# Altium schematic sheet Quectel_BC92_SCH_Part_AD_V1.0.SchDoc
size 840 x 594 mm
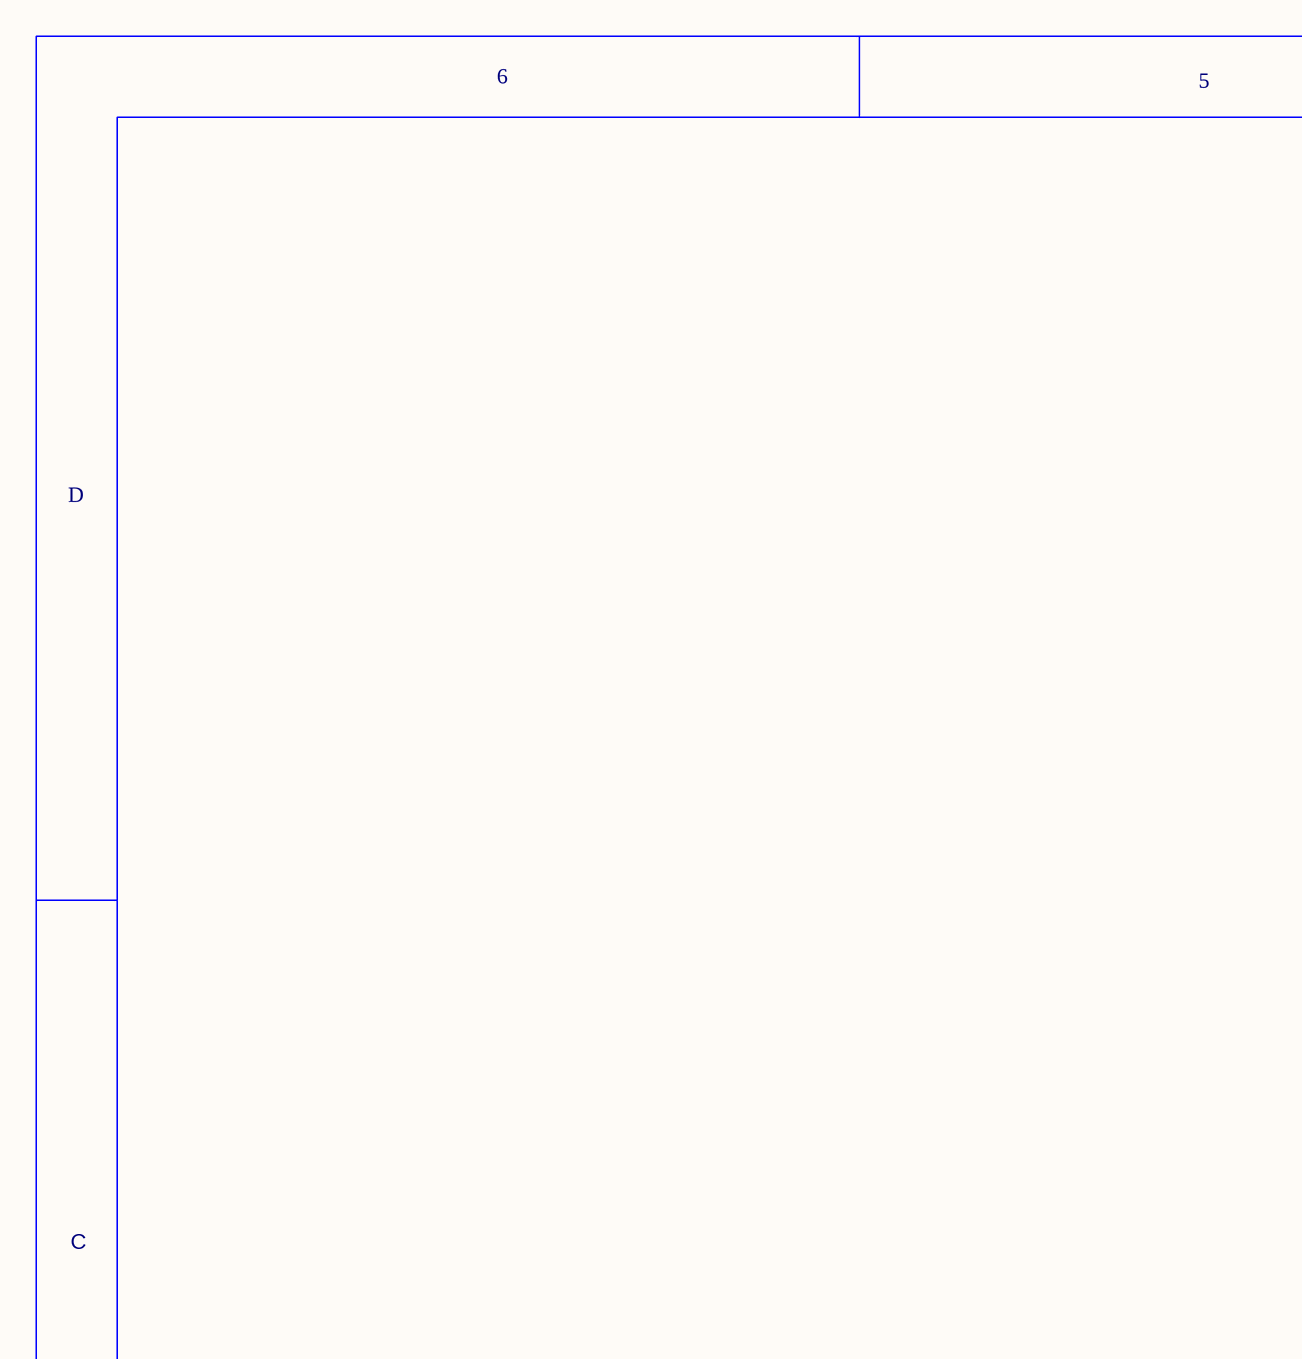
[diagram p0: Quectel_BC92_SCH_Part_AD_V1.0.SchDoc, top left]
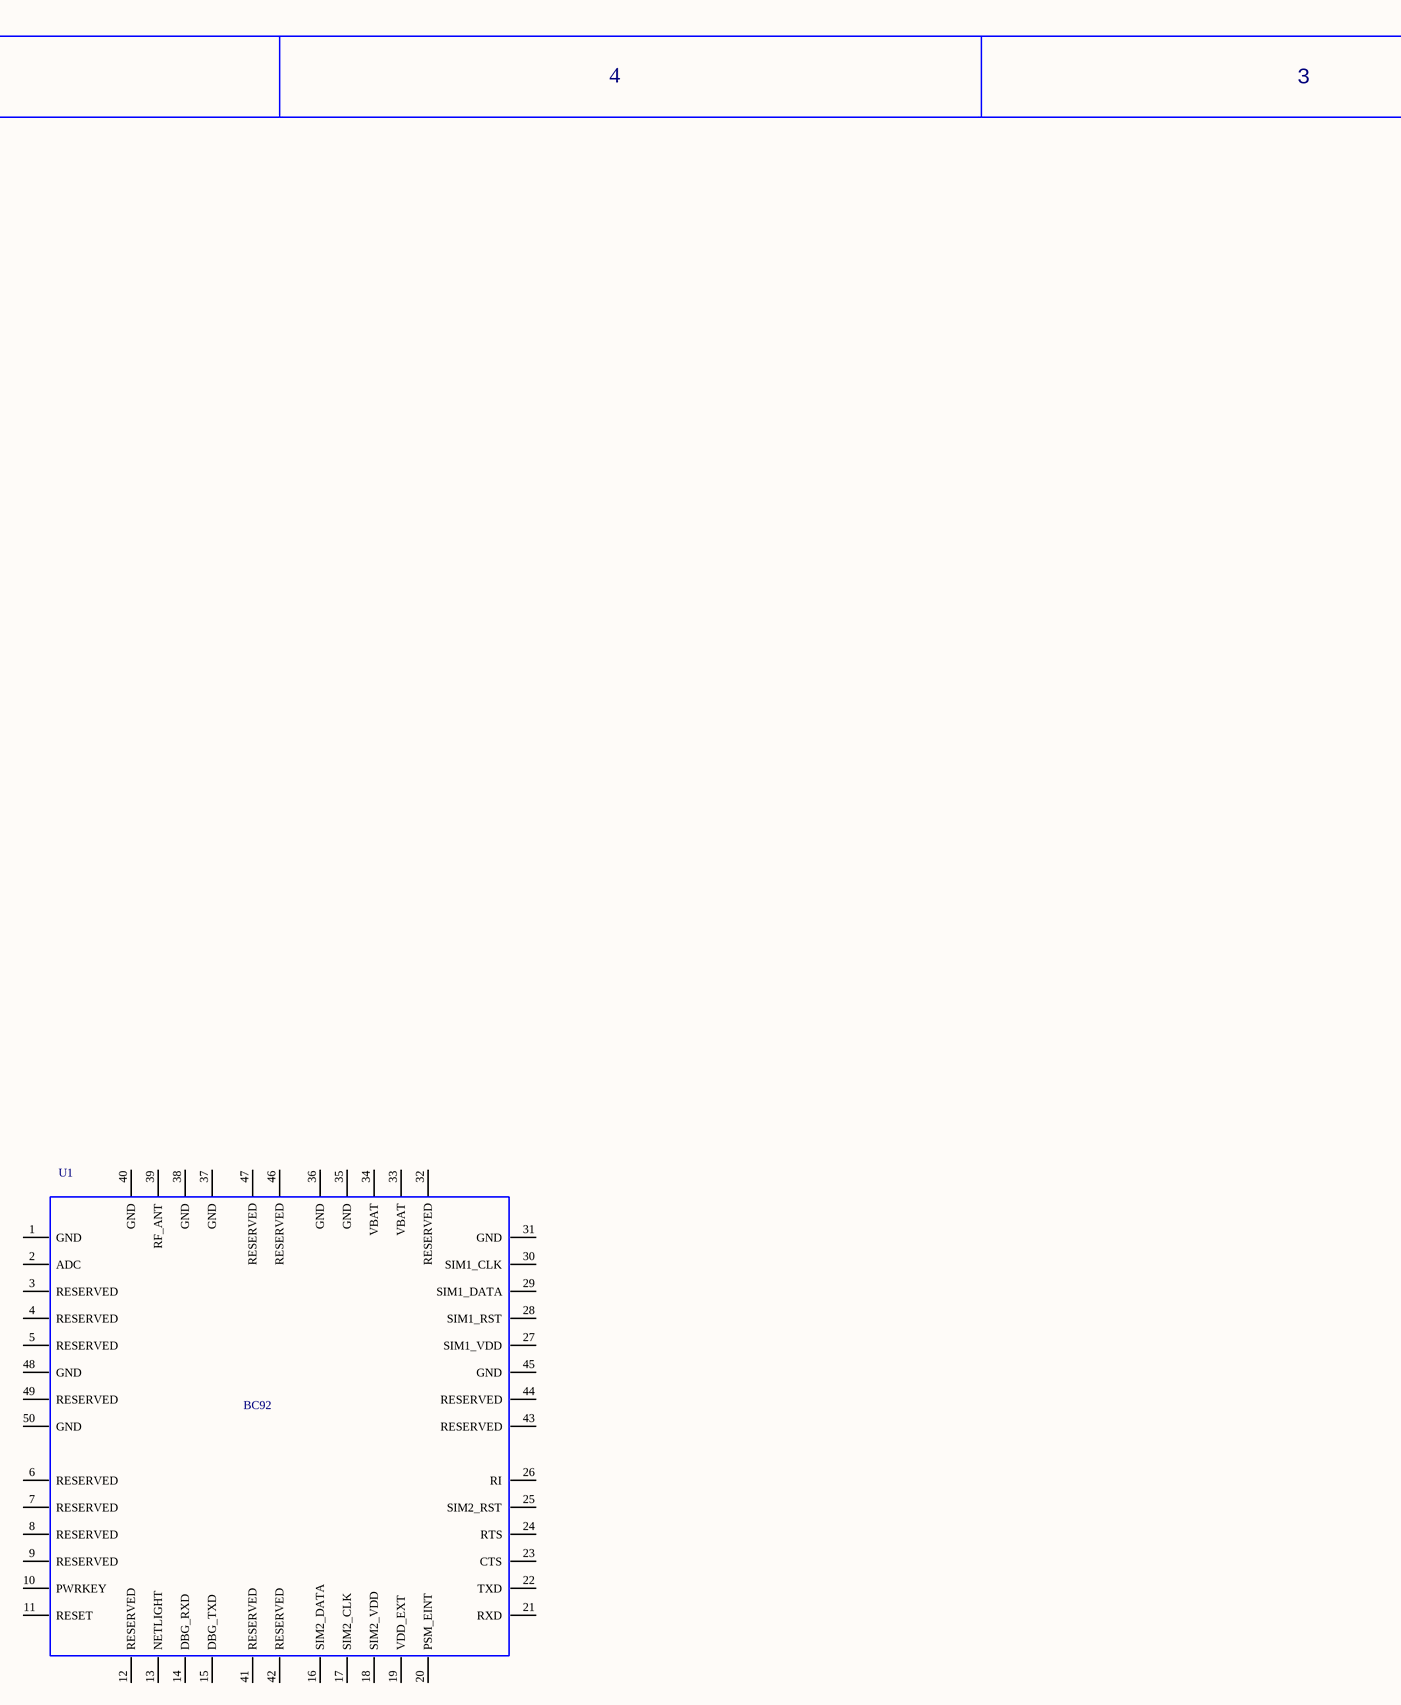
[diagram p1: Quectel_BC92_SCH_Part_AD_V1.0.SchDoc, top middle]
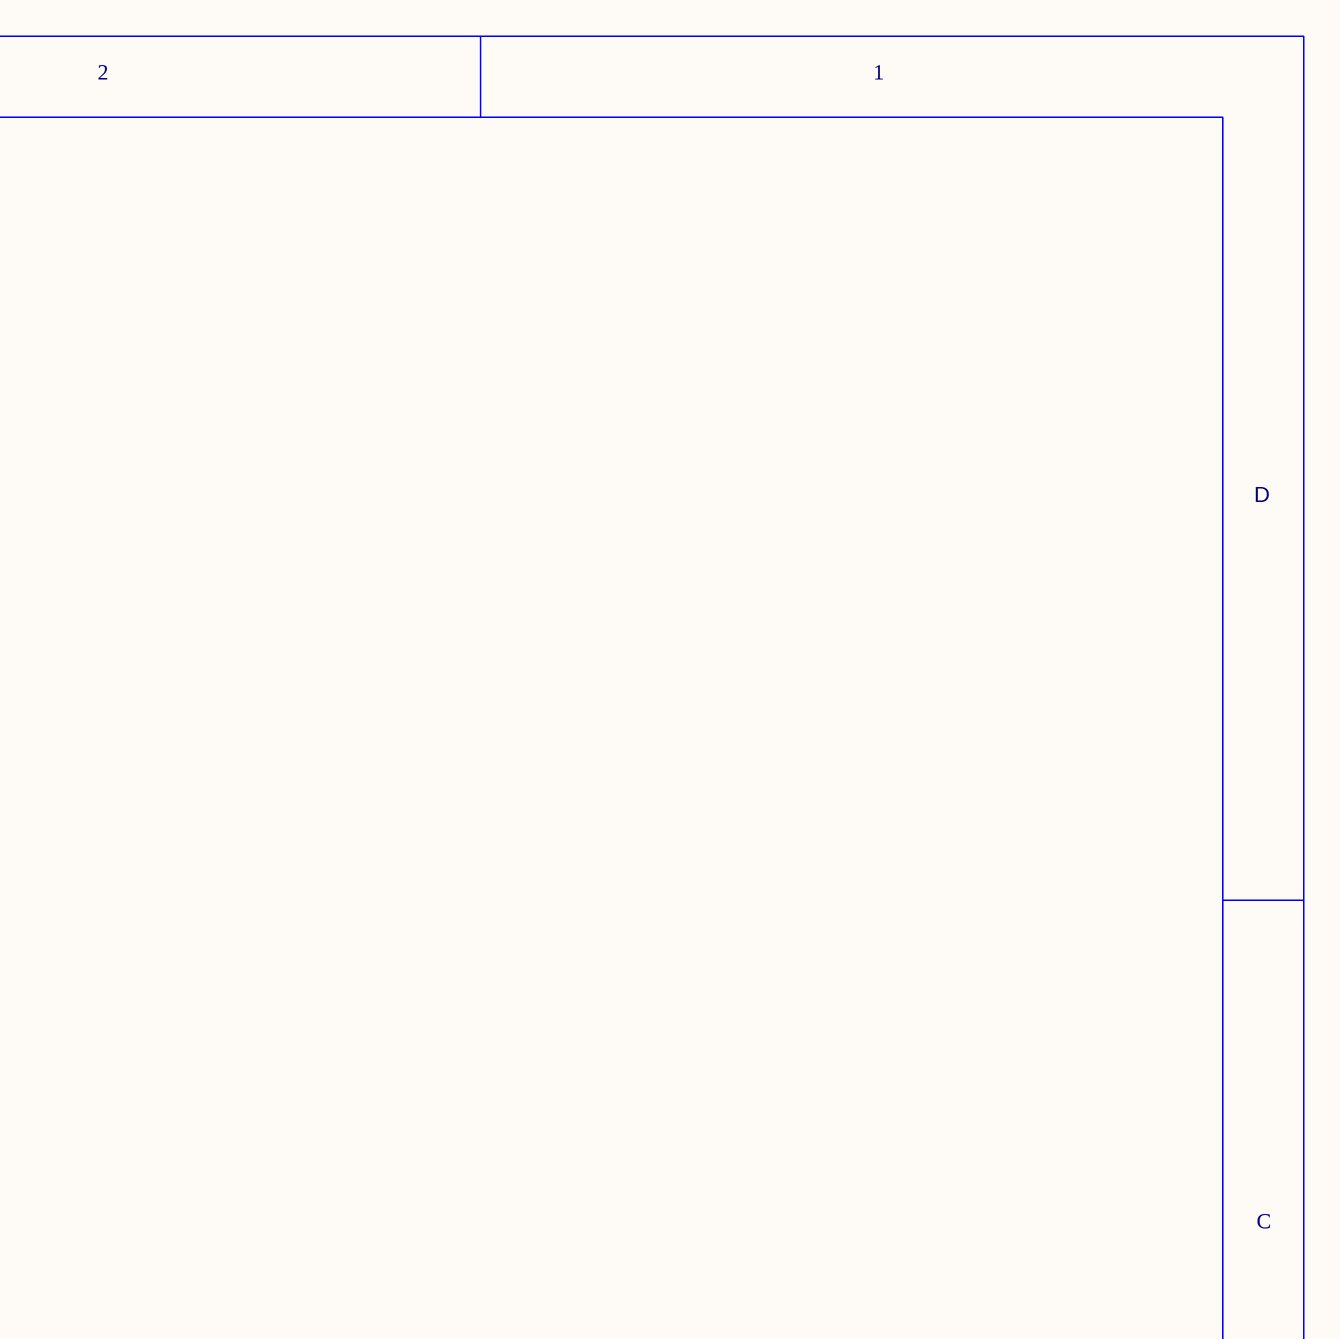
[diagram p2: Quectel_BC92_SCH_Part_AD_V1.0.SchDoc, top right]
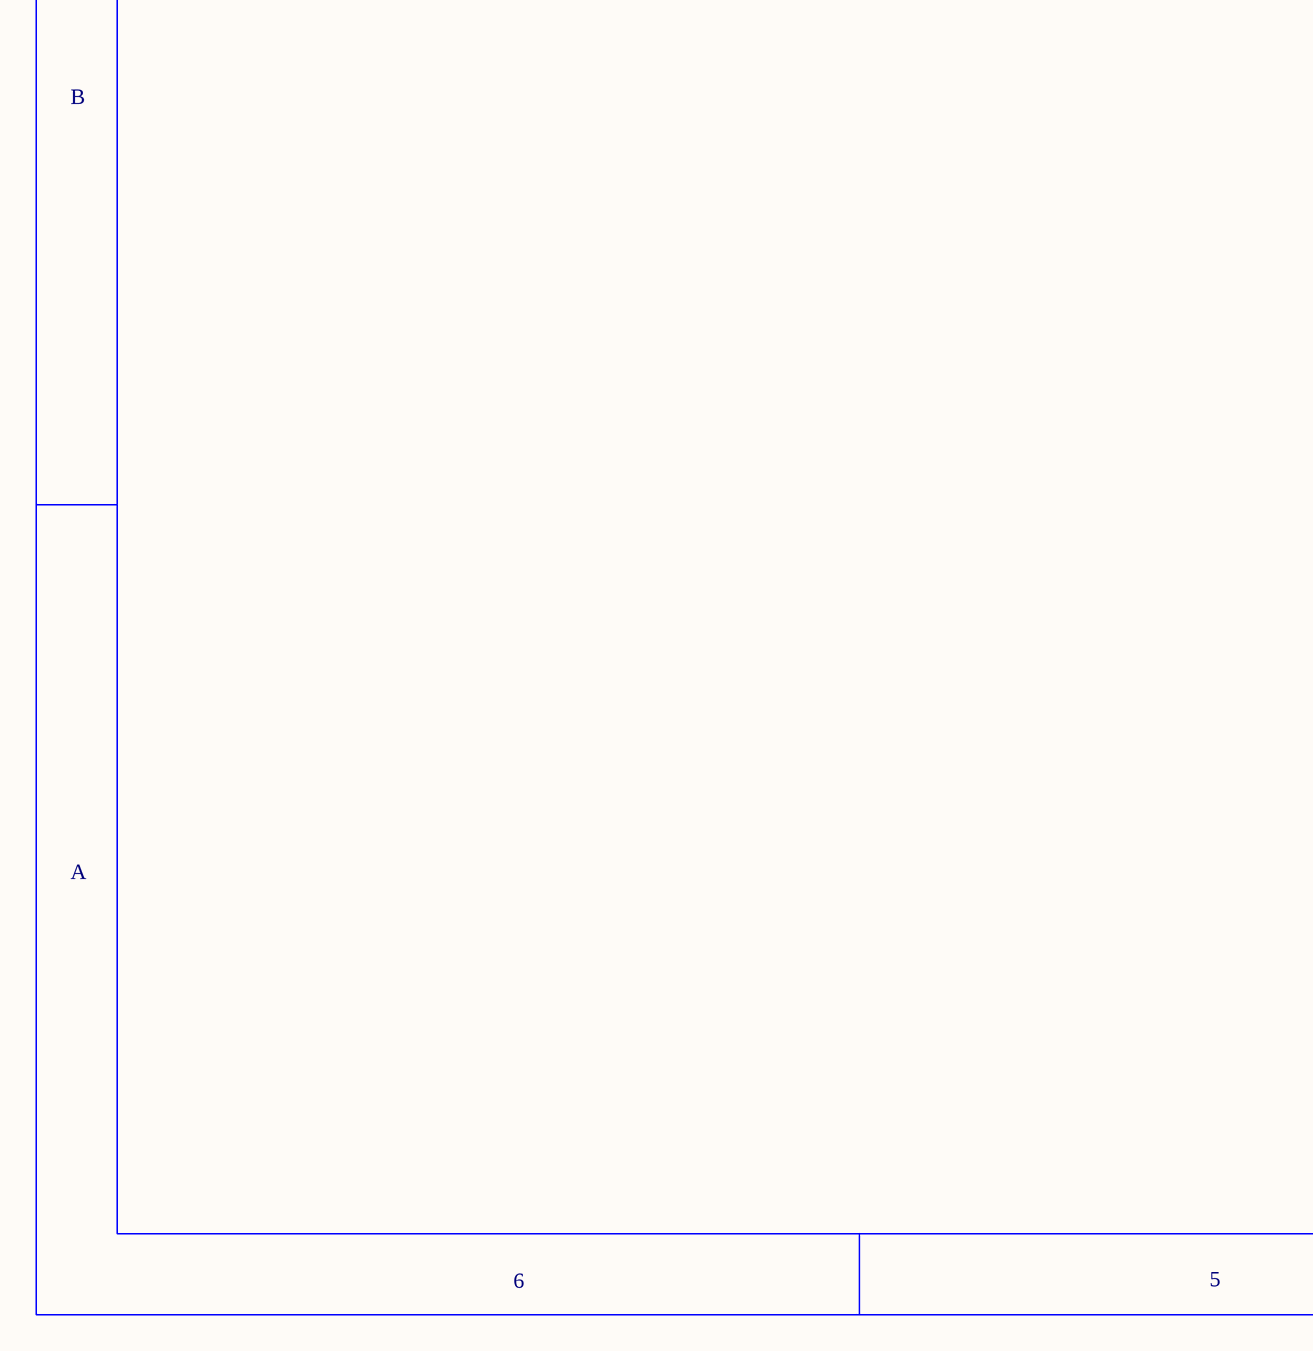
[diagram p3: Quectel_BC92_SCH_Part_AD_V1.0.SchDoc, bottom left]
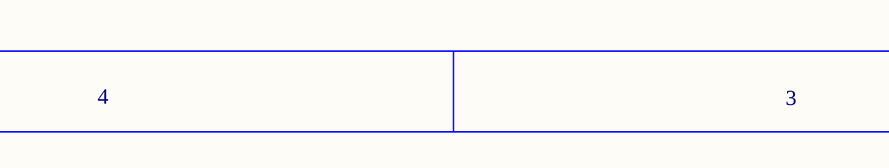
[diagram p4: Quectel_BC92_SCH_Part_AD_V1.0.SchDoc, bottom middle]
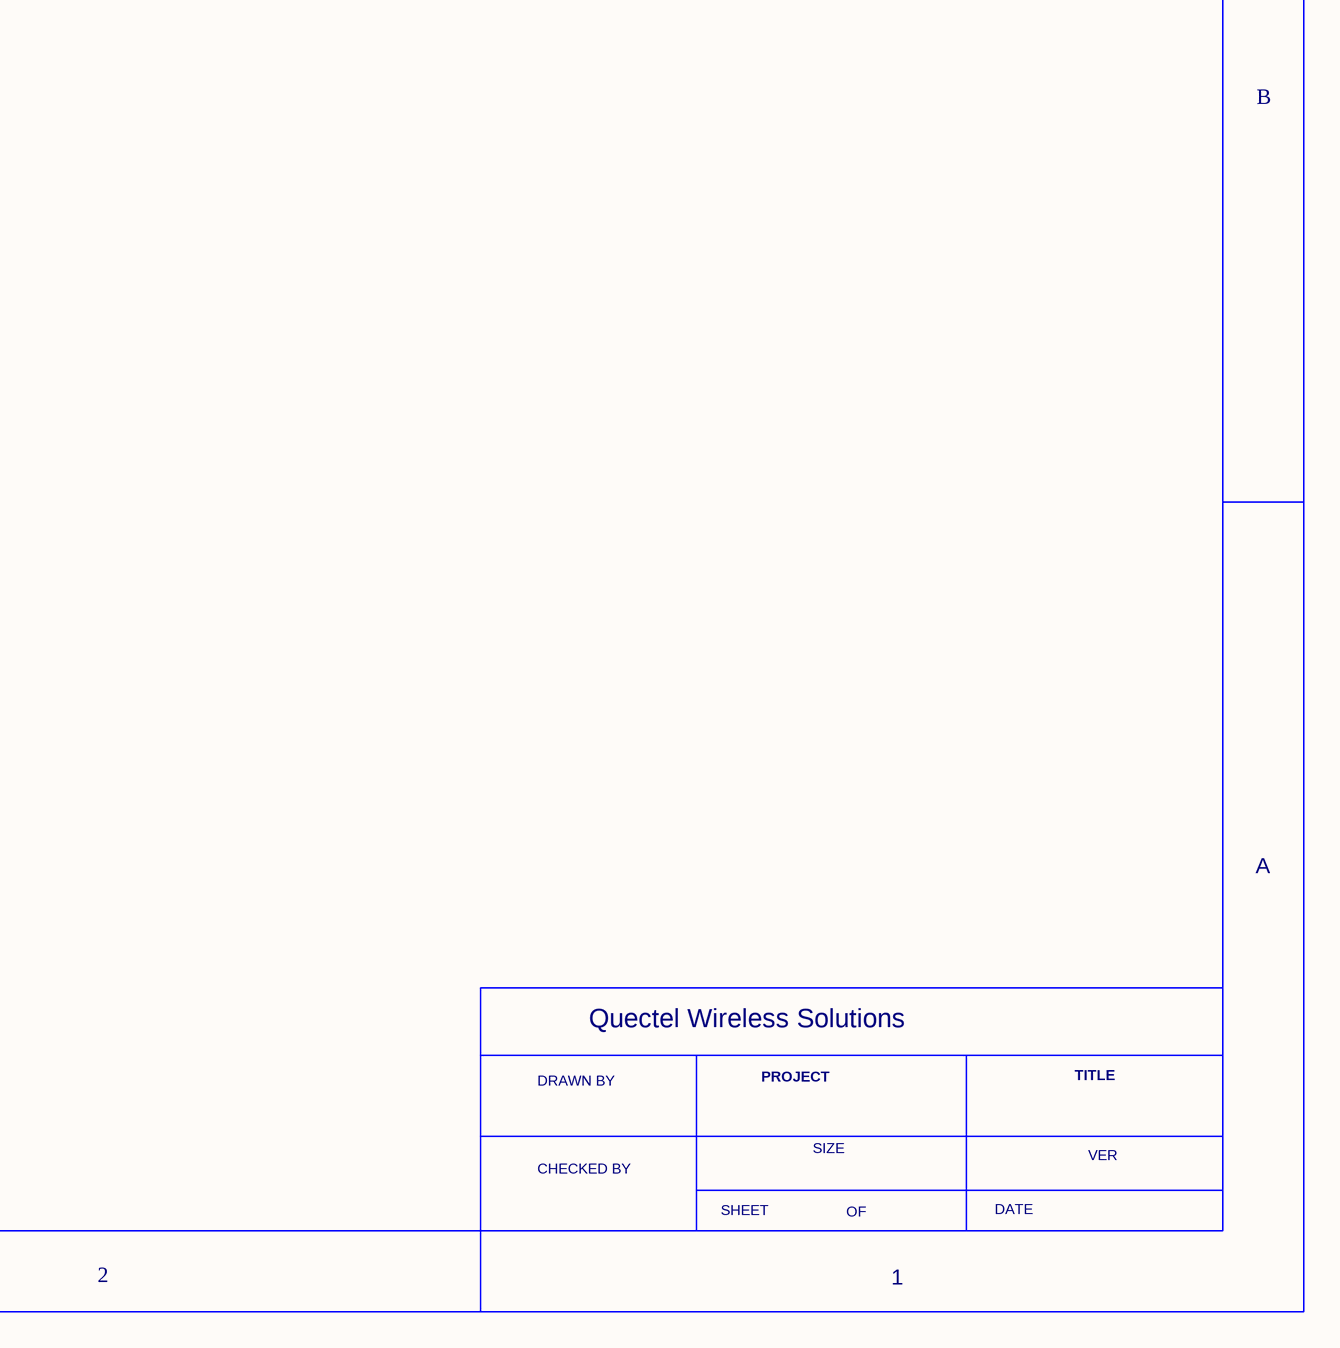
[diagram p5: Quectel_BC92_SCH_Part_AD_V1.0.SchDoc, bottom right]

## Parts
U1  BC92

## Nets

Not connected (* = marked no-connect by the designer): U1 1(GND) 2(ADC) 3(RESERVED) 4(RESERVED) 5(RESERVED) 6(RESERVED) 7(RESERVED) 8(RESERVED) 9(RESERVED) 10(PWRKEY) 11(RESET) 12(RESERVED) 13(NETLIGHT) 14(DBG_RXD) 15(DBG_TXD) 16(SIM2_DATA) 17(SIM2_CLK) 18(SIM2_VDD) 19(VDD_EXT) 20(PSM_EINT) 21(RXD) 22(TXD) 23(CTS) 24(RTS) 25(SIM2_RST) 26(RI) 27(SIM1_VDD) 28(SIM1_RST) 29(SIM1_DATA) 30(SIM1_CLK) 31(GND) 32(RESERVED) 33(VBAT) 34(VBAT) 35(GND) 36(GND) 37(GND) 38(GND) 39(RF_ANT) 40(GND) 41(RESERVED) 42(RESERVED) 43(RESERVED) 44(RESERVED) 45(GND) 46(RESERVED) 47(RESERVED) 48(GND) 49(RESERVED) 50(GND)

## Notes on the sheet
- 6
- 5
- 4
- 3
- 2
- 1
- D
- C
- B
- A
- Quectel Wireless Solutions
- DRAWN BY
- PROJECT
- TITLE
- CHECKED BY
- SIZE
- VER
- SHEET
- OF
- DATE

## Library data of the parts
U1 = BC92: NB-IoT Module BC92 23.6x19.9mm H2.2mm RO; Manufacturer: Quectel; Geometry.Height: 2.2mm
